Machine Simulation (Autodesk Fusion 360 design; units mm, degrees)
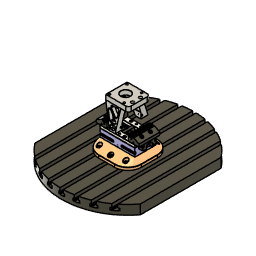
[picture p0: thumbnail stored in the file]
parameter "minJawOpening" = -31.6941 comment "Minimum Jaw Opening"
parameter "maxJawOpening" = 0 comment "Maximum Jaw Opening"
parameter "stockX" = 165.1 comment "Stock in X"
parameter "stockY" = 114.3 comment "Stock in Y"
parameter "stockZ" = 120.65 comment "Stock in Z"
base_feature "Base Feature1" OffsetX 0 OffsetY 0 OffsetZ 0 AngleZ 0
base_feature "Base Feature1"
base_feature "Base Feature1"
base_feature "Base Feature1"
base_feature "Base Feature1"
base_feature "Base Feature1"
base_feature "Base Feature1"
base_feature "Base Feature1"
base_feature "Base Feature1" OffsetX 0 OffsetY 0 OffsetZ 0 AngleZ 0 OffsetX 0 OffsetY 0 OffsetZ 0 AngleZ 0 OffsetX 0 OffsetY 0 OffsetZ 0 AngleZ 0 OffsetX 0 OffsetY 0 OffsetZ 0 AngleZ 0 OffsetX 0 OffsetY 0 OffsetZ 0 AngleZ 0
base_feature "Base Feature1" OffsetX 0 OffsetY 0 OffsetZ 0 AngleZ 0 OffsetX 0 OffsetY 0 OffsetZ 0 AngleZ 0 OffsetX 0 OffsetY 0 OffsetZ 0 AngleZ 0 OffsetX 0 OffsetY 0 OffsetZ 0 AngleZ 0 OffsetX 0 OffsetY 0 OffsetZ 0 AngleZ 0
base_feature "Base Feature1"
base_feature "Base Feature1"
base_feature "Base Feature1"
base_feature "Base Feature1"
as_built_joint "As-built1"
as_built_joint "As-built1"
as_built_joint "As-built1"
as_built_joint "As-built1"
as_built_joint "As-built1"
as_built_joint "As-built1"
joint "Assemble1" alignAngle 0 alignOffsetX 0 alignOffsetY 0 alignOffsetZ 0
as_built_joint "As-built3"
as_built_joint "As-built5"
as_built_joint "As-built6" OffsetX 0 OffsetY 0 OffsetZ 0 AngleZ 0
as_built_joint "As-built7" OffsetX 0 OffsetY 0 OffsetZ 0 AngleZ 0
work_plane "WorkPlane1" AlongDistance 0
joint_origin "JointOrigin1" OffsetX 0 OffsetY 0 OffsetZ 75.463 AngleZ 0
sketch "Sketch1" plane through (0, 0, 0) normal (0, 1, 0) x axis (1, 0, 0)
  line L1 (-15.24, -30.48) -> (-180.34, -30.48)
  line L2 (-15.24, 83.82) -> (-15.24, -30.48)
  line L3 (-180.34, 83.82) -> (-15.24, 83.82)
  line L4 (-180.34, -30.48) -> (-180.34, 83.82)
  point P2 (-180.34, -30.48)
  point P5 (-180.34, 83.82)
  point P3 (-15.24, -30.48)
  horizontal L1
  vertical L2
  horizontal L3
  vertical L4
  dimension "d111" distance P2 P5 = 114.3 (= "stockY")
  dimension "d112" distance P2 P3 = 165.1 (= "stockX")
  dimension "d318" OffsetX = 0
  dimension "d319" OffsetY = 0
  dimension "d320" OffsetZ = 0
  dimension "d321" AngleZ = 0
extrude "Extrude1" new body sketch "Sketch1" along normal blind 120.65 (= "stockZ")
joint_origin "JointOrigin1" OffsetX 0 OffsetY 0 OffsetZ 0 AngleZ 0
joint "Assemble2" alignAngle 0 alignOffsetX 0 alignOffsetY 0 alignOffsetZ 0
motion_link "MotionLink1" Value1 10.0076 Value2 10.0076
joint "Assemble3" alignAngle 180 alignOffsetX 0 alignOffsetY 0 alignOffsetZ 101.6 (= "stockY - 0.5 in")
base_feature "Base Feature1"
base_feature "Base Feature1"
joint "Assemble4" alignAngle 180 alignOffsetX 0 alignOffsetY 0 alignOffsetZ 0
joint "Assemble5" alignAngle 0 alignOffsetX 0 alignOffsetY 0 alignOffsetZ 0
base_feature "Base Feature1"
joint "Assemble6" alignAngle -90 alignOffsetX 0 alignOffsetY 0 alignOffsetZ 0
base_feature "Base Feature1"
joint_origin "JointOrigin1" OffsetX 0 named "d201_1" OffsetY 0 named "d202_1" OffsetZ 0 named "d203_1" AngleZ 0 named "d204_1"
base_feature "Base Feature1"
joint_origin "JointOrigin1" OffsetX 0 named "d201_2" OffsetY 0 named "d202_2" OffsetZ 0 named "d203_2" AngleZ 0 named "d204_2"
joint "Assemble7" alignAngle -90 alignOffsetX 0 alignOffsetY 0 alignOffsetZ 0
joint "Assemble8" alignAngle -90 alignOffsetX 0 alignOffsetY 0 alignOffsetZ 0
copy_paste "CutPaste1"
copy_paste "CutPaste2"
copy_paste "CutPaste1"
copy_paste "CutPaste2"
copy_paste "CutPaste3"
base_feature "Base Feature1"
joint_origin "JointOrigin1" OffsetX 0 named "d201_2_1" OffsetY 0 named "d202_2_1" OffsetZ 0 named "d203_2_1" AngleZ 0 named "d204_2_1"
joint_origin "JointOrigin2" OffsetX 0 named "d213_1" OffsetY 0 named "d214_1" OffsetZ 0 named "d215_1" AngleZ 0 named "d216_1"
base_feature "Base Feature1"
joint_origin "JointOrigin1" OffsetX 0 named "d201_3" OffsetY 0 named "d202_3" OffsetZ 0 named "d203_3" AngleZ 0 named "d204_3"
base_feature "Base Feature1"
joint_origin "JointOrigin1" OffsetX 0 named "d201_1_1" OffsetY 0 named "d202_1_1" OffsetZ 0 named "d203_1_1" AngleZ 0 named "d204_1_1"
joint_origin "JointOrigin2" OffsetX 0 named "d225_1" OffsetY 0 named "d226_1" OffsetZ 0 named "d227_1" AngleZ 0 named "d228_1"
joint "Assemble9" alignAngle 90 alignOffsetX 0 alignOffsetY 0 alignOffsetZ 0
joint "Assemble10" alignAngle 90 alignOffsetX 0 alignOffsetY 0 alignOffsetZ 0
joint "Assemble11" alignAngle 90 alignOffsetX 0 alignOffsetY 0 alignOffsetZ 0
copy_paste "CutPaste4"
copy_paste "CutPaste5"
copy_paste "CutPaste6"
base_feature "Base Feature1" OffsetX 0 OffsetY 0 OffsetZ 0 AngleZ 0 bodies "Table"
joint_origin "JointOrigin1" OffsetX 0 named "d149_1" OffsetY 0 named "d150_1" OffsetZ 0 named "d151_1" AngleZ 0 named "d152_1"
joint_origin "JointOrigin2" OffsetX 0 named "d153_1" OffsetY 0 named "d154_1" OffsetZ 0 named "d155_1" AngleZ 0 named "d156_1"
joint_origin "JointOrigin3" OffsetX 0 named "d157_1" OffsetY 0 named "d158_1" OffsetZ 0 named "d159_1" AngleZ 0 named "d160_1"
joint_origin "JointOrigin4" OffsetX 0 named "d161_1" OffsetY 0 named "d162_1" OffsetZ 0 named "d163_1" AngleZ 0 named "d164_1"
joint_origin "JointOrigin5" OffsetX 0 named "d165_1" OffsetY 0 named "d166_1" OffsetZ 0 named "d167_1" AngleZ 0 named "d168_1"
joint_origin "JointOrigin6" OffsetX 0 named "d169_1" OffsetY 0 named "d170_1" OffsetZ 0 named "d171_1" AngleZ 0 named "d172_1"
joint_origin "JointOrigin7" OffsetX 0 named "d173_1" OffsetY 0 named "d174_1" OffsetZ 0 named "d175_1" AngleZ 0 named "d176_1"
joint_origin "JointOrigin8" OffsetX 0 named "d177_1" OffsetY 0 named "d178_1" OffsetZ 0 named "d179_1" AngleZ 0 named "d180_1"
joint_origin "JointOrigin9" OffsetX 0 named "d181_1" OffsetY 0 named "d182_1" OffsetZ 0 named "d183_1" AngleZ 0 named "d184_1"
joint_origin "JointOrigin10" OffsetX 0 named "d185_1" OffsetY 0 named "d186_1" OffsetZ 0 named "d187_1" AngleZ 0 named "d188_1"
joint_origin "JointOrigin11" OffsetX 0 named "d189_1" OffsetY 0 named "d190_1" OffsetZ 0 named "d191_1" AngleZ 0 named "d192_1"
joint_origin "JointOrigin12" OffsetX 0 named "d193_1" OffsetY 0 named "d194_1" OffsetZ 0 named "d195_1" AngleZ 0 named "d196_1"
joint_origin "JointOrigin13" OffsetX 0 named "d197_1" OffsetY 0 named "d198_1" OffsetZ 0 named "d199_1" AngleZ 0 named "d200_1"
joint_origin "JointOrigin14" OffsetX 0 named "d201_4" OffsetY 0 named "d202_4" OffsetZ 0 named "d203_4" AngleZ 0 named "d204_4"
joint_origin "JointOrigin15" OffsetX 0 named "d205_1" OffsetY 0 named "d206_1" OffsetZ 0 named "d207_1" AngleZ 0 named "d208_1"
joint_origin "JointOrigin16" OffsetX 0 named "d209_1" OffsetY 0 named "d210_1" OffsetZ 0 named "d211_1" AngleZ 0 named "d212_1"
joint_origin "JointOrigin17" OffsetX 0 named "d213_2" OffsetY 0 named "d214_2" OffsetZ 0 named "d215_2" AngleZ 0 named "d216_2"
joint_origin "JointOrigin18" OffsetX 0 named "d217_1" OffsetY 0 named "d218_1" OffsetZ 0 named "d219_1" AngleZ 0 named "d220_1"
as_built_joint "As-built1"
joint "Assemble12" alignAngle 90 alignOffsetX 0 alignOffsetY 0 alignOffsetZ 38.1 (= "4 in - 2.5 in")
copy_paste "CutPaste1"
sketch "Sketch1" plane through (0, 0, 0) normal (0, -1, 0) x axis (1, 0, 0)
  line L1 (-50, 82.4998) -> (50, 82.4998)
  line L2 (-50, -82.4998) -> (-50, 82.4998)
  line L3 (50, -82.4998) -> (-50, -82.4998)
  line L4 (50, 82.4998) -> (50, -82.4998)
  line L5 (-50, -82.4998) -> (50, 82.4998)
  line L6 (50, -82.4998) -> (-50, 82.4998)
  point P6 (0, 0)
  point P1 (0, 0)
  point P2 (50, 82.4998)
  point P7 (50, 82.4998)
  perpendicular L1 L2
  parallel L1 L3
  parallel L2 L4
  horizontal L1
  coincident L5 P6
  coincident L6 P6
  coincident P1 P6
  coincident P2 P7
  dimension "d358" OffsetX = 0
  dimension "d359" OffsetY = 0
  dimension "d360" OffsetZ = 0
  dimension "d361" AngleZ = 0
extrude "Extrude1" new body sketch "Sketch1" profile of L1 L2 L3 L4 along normal blind 3.81
sketch "Sketch2" plane through (0, -38.1, 0) normal (0, 1, 0) x axis (-1, 0, 0)
  line L1 (-101.6, 101.6) -> (101.6, 101.6)
  line L2 (-101.6, -101.6) -> (-101.6, 101.6)
  line L3 (101.6, -101.6) -> (-101.6, -101.6)
  line L4 (101.6, 101.6) -> (101.6, -101.6)
  line L5 (-101.6, -101.6) -> (101.6, 101.6)
  line L6 (101.6, -101.6) -> (-101.6, 101.6)
  point P6 (0, 0)
  point P1 (0, 0)
  point P2 (101.6, 101.6)
  point P3 (-101.6, 101.6)
  perpendicular L1 L2
  parallel L1 L3
  parallel L2 L4
  horizontal L1
  coincident L5 P6
  coincident L6 P6
  coincident P1 P6
  equal L1 L4
  dimension "d287" distance P2 P3 = 203.2
extrude "Extrude2" new body sketch "Sketch2" profile of L1 L2 L3 L4 along normal blind 12.7
fillet "Fillet1" radius 63.5
fillet "Fillet2" radius 1.27
loft "Loft1"
sketch "Sketch3" plane through (0, -38.1, 0) normal (0, -1, 0) x axis (1, 0, 0)
  circle C1 centre (0, 0) radius 28.575
  point P1 (0, 0)
  point P2 (0, 0)
  coincident P1 P2
  dimension "d292" diameter C1 = 57.15
extrude "Extrude3" add sketch "Sketch3" along normal blind 6.35
as_built_joint "As-built8"
as_built_joint "As-built9"
sketch "Sketch2" plane through (0, 0, 0) normal (0, 0, 1) x axis (1, 0, 0)
  line L1 (482.6, 147.0957) -> (179.3748, 147.0957)
  line L2 (482.6, 58.1957) -> (482.6, 147.0957)
  line L3 (444.5, 58.1957) -> (482.6, 58.1957)
  line L4 (444.5, 80.4207) -> (444.5, 58.1957)
  line L5 (333.375, 80.4207) -> (444.5, 80.4207)
  line L6 (333.375, 110.2657) -> (333.375, 80.4207)
  line L7 (320.675, 110.2657) -> (333.375, 110.2657)
  line L8 (320.675, 115.3457) -> (320.675, 110.2657)
  line L9 (307.34, 115.3457) -> (320.675, 115.3457)
  line L10 (305.054, 124.7183) -> (307.34, 115.3457)
  line L11 (264.414, 124.7183) -> (305.054, 124.7183)
  line L12 (264.414, 128.4267) -> (264.414, 124.7183)
  line L13 (261.1628, 128.4267) -> (264.414, 128.4267)
  line L14 (261.1628, 124.7183) -> (261.1628, 128.4267)
  line L15 (255.5748, 124.7183) -> (261.1628, 124.7183)
  line L16 (255.5748, 127.1186) -> (255.5748, 124.7183)
  line L17 (217.4748, 127.1186) -> (255.5748, 127.1186)
  line L18 (217.4748, 140.7457) -> (217.4748, 127.1186)
  line L19 (179.3748, 140.7457) -> (217.4748, 140.7457)
  line L20 (179.3748, 147.0957) -> (179.3748, 140.7457)
  point P2 (179.3748, 147.0957)
  point P22 (179.3748, 147.0957)
  point P3 (482.6, 147.0957)
  point P4 (482.6, 58.1957)
  point P14 (264.414, 128.4267)
  point P15 (261.1628, 128.4267)
  point P5 (444.5, 58.1957)
  point P6 (444.5, 80.4207)
  point P7 (333.375, 80.4207)
  point P8 (333.375, 110.2657)
  point P9 (320.675, 110.2657)
  point P10 (320.675, 115.3457)
  point P11 (307.34, 115.3457)
  point P12 (305.054, 124.7183)
  point P13 (264.414, 124.7183)
  point P16 (261.1628, 124.7183)
  point P17 (255.5748, 124.7183)
  point P20 (217.4748, 140.7457)
  point P21 (179.3748, 140.7457)
  point P18 (255.5748, 127.1186)
  point P19 (217.4748, 127.1186)
  horizontal L1
  perpendicular L1 L2
  perpendicular L2 L3
  perpendicular L1 L4
  perpendicular L2 L5
  perpendicular L1 L6
  perpendicular L6 L7
  perpendicular L7 L8
  perpendicular L8 L9
  perpendicular L8 L11
  perpendicular L11 L12
  perpendicular L12 L13
  perpendicular L13 L14
  perpendicular L14 L15
  perpendicular L15 L16
  collinear L11 L15
  perpendicular L17 L18
  perpendicular L18 L19
  perpendicular L19 L20
  coincident P2 P22
  dimension "d295" distance P3 P4 = 88.9
  dimension "d296" distance L1 L5 = 66.675 (= "( 5.25 / 2 ) * 1 in")
  dimension "d297" distance L1 L7 = 36.83 (= "( 2.9 / 2 ) * 1 in")
  dimension "d298" distance L1 L9 = 31.75 (= "( 2.5 / 2 ) * 1 in")
  dimension "d299" distance L1 L11 = 22.3774 (= "( 1.762 / 2 ) * 1 in")
  dimension "d300" distance L1 L13 = 18.669 (= "( 1.47 / 2 ) * 1 in")
  dimension "d301" distance L1 L17 = 19.9771 (= "( 1.573 / 2 ) * 1 in")
  dimension "d302" distance P14 P15 = 3.2512
  dimension "d303" distance P4 P5 = 38.1
  dimension "d304" distance P6 P7 = 111.125
  dimension "d305" distance P8 P9 = 12.7
  dimension "d306" distance P10 P11 = 13.335
  dimension "d307" distance P11 P12 = 2.286
  dimension "d308" distance P12 P13 = 40.64
  dimension "d309" distance P16 P17 = 5.588
  dimension "d310" distance L1 L19 = 6.35
  dimension "d311" distance P20 P21 = 38.1
  dimension "d312" distance P18 P19 = 38.1
revolve "Revolve1" sketch "Sketch2" AlongAngle 360
component_from_bodies "Body->Comp"
joint "Assemble13" alignAngle 180 alignOffsetX 0 alignOffsetY -15.24 alignOffsetZ -12.7
copy_paste "CutPaste2"
copy_paste "CutPaste3"
sketch "Sketch4" plane through (0, -38.1, 0) normal (0, -1, 0) x axis (1, 0, 0)
  line L1 (-191.6377, 250) -> (191.6377, 250)
  line L2 (191.6377, -250) -> (-191.6377, -250)
  line L3 (310.1389, -55.126) -> (9.652, -55.126)
  line L4 (9.652, -70.874) -> (306.9232, -70.874)
  circle C1 centre (-73.025, 63) radius 6.6675
  circle C2 centre (73.025, 63) radius 6.6675
  circle C3 centre (82.55, 0) radius 6.6675
  circle C4 centre (-82.55, 0) radius 6.6675
  circle C5 centre (-73.025, -63) radius 6.6675
  circle C6 centre (73.025, -63) radius 6.6675
  arc A1 centre (0, 0) radius 315 clockwise from (191.6377, 250) to (191.6377, -250)
  arc A2 centre (0, 0) radius 315 clockwise from (-191.6377, -250) to (-191.6377, 250)
  circle C7 centre (59.8029, -16.0241) radius 6.7437
  circle C8 centre (-16.0241, -59.8029) radius 6.7437
  circle C9 centre (-43.7787, -43.7787) radius 6.7437
  circle C10 centre (-43.7787, 43.7787) radius 6.7437
  circle C11 centre (-16.0241, 59.8029) radius 6.7437
  circle C12 centre (59.8029, 16.0241) radius 6.7437
  circle C13 centre (0, 0) radius 0.4391
  arc A3 centre (-60.96, 63) radius 7.874 clockwise from (-60.96, 70.874) to (-60.96, 55.126)
  arc A4 centre (9.652, 63) radius 7.874 clockwise from (9.652, 55.126) to (9.652, 70.874)
  arc A5 centre (9.652, -63) radius 7.874 clockwise from (9.652, -70.874) to (9.652, -55.126)
  arc A6 centre (0, 0) radius 315 clockwise from (310.1389, -55.126) to (306.9232, -70.874)
  arc A7 centre (-60.96, -63) radius 7.874 clockwise from (-60.96, -55.126) to (-60.96, -70.874)
  arc A8 centre (-42.672, 0) radius 7.874 clockwise from (-42.672, 7.874) to (-42.672, -7.874)
  arc A9 centre (80.01, 0) radius 7.874 clockwise from (80.01, -7.874) to (80.01, 7.874)
  point P3 (73.025, 63)
  point P24 (9.652, 63)
  point P2 (-73.025, 63)
  point P7 (73.025, -63)
  point P27 (9.652, -63)
  point P6 (-73.025, -63)
  point P4 (82.55, 0)
  point P39 (80.01, 0)
  point P5 (-82.55, 0)
  point P36 (-42.672, 0)
  point P1 (0, 0)
  equal C5 C6
  equal C4 C5
  equal C1 C4
  equal C1 C2
  equal C2 C3
  horizontal P3 P24
  horizontal P2 P3
  horizontal P7 P27
  horizontal P6 P7
  vertical P2 P6
  vertical P3 P7
  horizontal P4 P39
  horizontal P5 P36
  dimension "d342" diameter C1 = 13.335
  dimension "d343" distance P1 P7 = 73.025
  dimension "d344" distance P1 P6 = 73.025 (= "d343")
  dimension "d346" distance P1 P5 = 82.55
  dimension "d347" distance P1 P4 = 82.55 (= "d346")
extrude "Extrude4" cut sketch "Sketch4" profile of C1 C2 C3 C4 C5 C6 A9 no distance stored
work_plane "WorkPlane1" AlongDistance -6.35
sketch "Sketch5" plane through (0, -31.75, 0) normal (0, -1, 0) x axis (1, 0, 0)
  circle C1 centre (73.025, 63) radius 9.8425
  circle C2 centre (73.025, 63) radius 6.6675
  circle C3 centre (82.55, 0) radius 9.8425
  circle C4 centre (73.025, -63) radius 9.8425
  circle C5 centre (-73.025, -63) radius 9.8425
  circle C6 centre (-82.55, 0) radius 9.8425
  circle C7 centre (-73.025, 63) radius 9.8425
  circle C8 centre (-73.025, 63) radius 6.6675
  circle C9 centre (-82.55, 0) radius 6.6675
  circle C10 centre (-73.025, -63) radius 6.6675
  circle C11 centre (73.025, -63) radius 6.6675
  circle C12 centre (82.55, 0) radius 6.6675
  concentric C1 C2
  equal C6 C7
  equal C5 C6
  equal C4 C5
  equal C3 C4
  equal C1 C3
  concentric C7 C8
  concentric C6 C9
  concentric C5 C10
  concentric C4 C11
  concentric C3 C12
  dimension "d349" diameter C1 = 19.685
extrude "Extrude5" cut sketch "Sketch5" no distance stored
chamfer "Chamfer1" distance 0.762
chamfer "Chamfer2" distance 0.762
base_feature "Base Feature1" OffsetX 0 OffsetY 0 OffsetZ 0 AngleZ 0
joint "Assemble14" alignAngle 0 alignOffsetX 0 alignOffsetY 0 alignOffsetZ 0
base_feature "Base Feature1" OffsetX 0 named "d354_1" OffsetY 0 named "d355_1" OffsetZ 0 named "d356_1" AngleZ 0 named "d357_1"
joint_origin "JointOrigin2" OffsetX 0 named "d366_1" OffsetY 0 named "d367_1" OffsetZ 0 named "d368_1" AngleZ 0 named "d369_1"
base_feature "Base Feature1" OffsetX 0 named "d354_2" OffsetY 0 named "d355_2" OffsetZ 0 named "d356_2" AngleZ 0 named "d357_2"
joint_origin "JointOrigin2" OffsetX 0 named "d366_2" OffsetY 0 named "d367_2" OffsetZ 0 named "d368_2" AngleZ 0 named "d369_2"
base_feature "Base Feature1" OffsetX 0 named "d354_3" OffsetY 0 named "d355_3" OffsetZ 0 named "d356_3" AngleZ 0 named "d357_3"
joint_origin "JointOrigin2" OffsetX 0 named "d366_3" OffsetY 0 named "d367_3" OffsetZ 0 named "d368_3" AngleZ 0 named "d369_3"
base_feature "Base Feature1" OffsetX 0 named "d354_4" OffsetY 0 named "d355_4" OffsetZ 0 named "d356_4" AngleZ 0 named "d357_4"
joint_origin "JointOrigin2" OffsetX 0 named "d366_4" OffsetY 0 named "d367_4" OffsetZ 0 named "d368_4" AngleZ 0 named "d369_4"
base_feature "Base Feature1" OffsetX 0 named "d354_5" OffsetY 0 named "d355_5" OffsetZ 0 named "d356_5" AngleZ 0 named "d357_5"
joint_origin "JointOrigin2" OffsetX 0 named "d366_5" OffsetY 0 named "d367_5" OffsetZ 0 named "d368_5" AngleZ 0 named "d369_5"
joint "Assemble15" alignAngle 0 alignOffsetX 0 alignOffsetY 0 alignOffsetZ 0
joint "Assemble16" alignAngle 0 alignOffsetX 0 alignOffsetY 0 alignOffsetZ 0
joint "Assemble17" alignAngle 0 alignOffsetX 0 alignOffsetY 0 alignOffsetZ 0
joint "Assemble18" alignAngle 0 alignOffsetX 0 alignOffsetY 0 alignOffsetZ 0
joint "Assemble19" alignAngle 0 alignOffsetX 0 alignOffsetY 0 alignOffsetZ 0
copy_paste "CutPaste4"
copy_paste "CutPaste5"
copy_paste "CutPaste6"
copy_paste "CutPaste7"
copy_paste "CutPaste8"
copy_paste "CutPaste9"
sketch "Sketch2" plane through (0, 0, 0) normal (0, -1, 0) x axis (1, 0, 0)
  line L1 (-50, 82.4998) -> (50, 82.4998)
  line L2 (-50, -82.4998) -> (-50, 82.4998)
  line L3 (50, -82.4998) -> (-50, -82.4998)
  line L4 (50, 82.4998) -> (50, -82.4998)
  line L5 (-50, -82.4998) -> (50, 82.4998)
  line L6 (50, -82.4998) -> (-50, 82.4998)
  point P6 (0, 0)
  point P1 (0, 0)
  point P2 (50, 82.4998)
  point P7 (50, 82.4998)
  perpendicular L1 L2
  parallel L1 L3
  parallel L2 L4
  horizontal L1
  coincident L5 P6
  coincident L6 P6
  coincident P1 P6
  coincident P2 P7
extrude "Extrude2" new body sketch "Sketch2" profile of L1 L2 L3 L4 along normal blind 2.54
fillet "Fillet2" radius 1.27
as_built_joint "As-built10"
remove_instance "RemoveInstance18"
base_feature "Base Feature1"
position "Position32"
joint "Assemble21" OffsetX 0 OffsetY 0 OffsetZ 0 AngleZ 0 alignAngle 180 alignOffsetX 0 alignOffsetY 0 alignOffsetZ -114.0572
as_built_joint "As-built12"
sketch "Side Containment" plane through (82.55, 0, 6.35) normal (1, 0, 0) x axis (0, 1, 0)
  line L1 (75.463, -63.5) -> (75.463, 50.8)
  line L2 (196.113, -63.5) -> (75.463, -63.5)
  line L3 (196.113, 50.8) -> (196.113, -63.5)
  line L4 (75.463, 50.8) -> (196.113, 50.8)
  line L5 (79.5905, 95.25) -> (231.9905, 95.25)
  line L6 (79.5905, 39.37) -> (79.5905, 95.25)
  line L7 (55.0926, 39.37) -> (79.5905, 39.37)
  line L8 (55.0926, -52.07) -> (55.0926, 39.37)
  line L9 (79.5905, -52.07) -> (55.0926, -52.07)
  line L10 (79.5905, -107.95) -> (79.5905, -52.07)
  line L11 (231.9905, -107.95) -> (79.5905, -107.95)
  line L12 (231.9905, 95.25) -> (231.9905, -107.95)
  line L13 (48.4465, 0) -> (48.4465, -12.7)
  line L14 (231.9905, -6.35) -> (48.4465, -6.35)
  line L15 (50.063, 44.45) -> (75.463, 44.45)
  line L16 (50.0126, 75.3878) -> (50.0126, -88.0878)
  line L17 (77.0505, 51.054) -> (77.0505, 63.246)
  point P16 (48.4465, -6.35)
  point P17 (231.9905, -6.35)
  point P6 (231.9905, 95.25)
  point P13 (231.9905, -107.95)
  point P7 (79.5905, 95.25)
  horizontal L5
  perpendicular L4 L6
  perpendicular L1 L7
  perpendicular L4 L8
  perpendicular L8 L9
  perpendicular L4 L10
  perpendicular L8 L11
  vertical L12
  midpoint L13 P16
  coincident L12 P17
  perpendicular L12 L14
  midpoint L12 P17
  equal L6 L10
  collinear L6 L10
  dimension "d464" distance L7 L15 = 5.08
  dimension "d465" distance L8 L16 = 5.08
  dimension "d466" distance L6 L17 = 2.54
  dimension "d467" distance P6 P13 = 203.2
  dimension "d468" distance P6 P7 = 152.4
base_feature "Base Feature1"
joint "Assemble22" OffsetX 0 OffsetY 0 OffsetZ 0 AngleZ 0 OffsetX 0 OffsetY 0 OffsetZ 0 AngleZ 0 alignAngle 0 alignOffsetX 0 alignOffsetY -6.35 alignOffsetZ 0
sketch "Sketch4" plane through (0, -38.1, 0) normal (0, 1, 0) x axis (-1, 0, 0)
  line L1 (245.7959, 197.001) -> (-245.7959, 197.001)
  line L2 (-191.6377, 250) -> (191.6377, 250)
  arc A1 centre (0, 0) radius 315 clockwise from (191.6377, 250) to (245.7959, 197.001)
  arc A2 centre (0, 0) radius 315 clockwise from (-245.7959, 197.001) to (-191.6377, 250)
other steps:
base_feature "Base Feature1" OffsetX 0 OffsetY 0 OffsetZ 0 AngleZ 0
create_component "CreateComponent1"
create_component "CreateComponent1"
create_component "CreateComponent2"
create_component "CreateComponent3"
create_component "CreateComponent4"
create_component "CreateComponent5"
create_component "CreateComponent6"
create_component "CreateComponent7"
create_component "CreateComponent2"
create_component "CreateComponent1"
create_component "CreateComponent2"
create_component "CreateComponent3"
create_component "CreateComponent1"
create_component "CreateComponent4"
create_component "CreateComponent1"
create_component "CreateComponent2"
create_component "CreateComponent5"
create_component "CreateComponent1"
create_component "CreateComponent6"
joint_origin "JointOrigin1" OffsetX 0 OffsetY 0 OffsetZ 0 AngleZ 0
joint_origin "JointOrigin1" OffsetX 0 OffsetY 0 OffsetZ 0 AngleZ 0
create_component "CreateComponent7"
joint_origin "JointOrigin6" OffsetX 0 OffsetY 0 OffsetZ 0 AngleZ 0
joint_origin "JointOrigin6" OffsetX 0 OffsetY 0 OffsetZ 0 AngleZ 0
create_component "CreateComponent8"
create_component "CreateComponent9"
joint_origin "JointOrigin1" OffsetX 0 OffsetY 0 OffsetZ 0 AngleZ 0
joint_origin "JointOrigin7" OffsetX 0 OffsetY 0 OffsetZ 0 AngleZ 0
joint_origin "JointOrigin1" OffsetX 0 OffsetY 0 OffsetZ 0 AngleZ 0
joint_origin "JointOrigin7" OffsetX 0 OffsetY 0 OffsetZ 0 AngleZ 0
create_component "CreateComponent10"
joint_origin "JointOrigin1" OffsetX 0 OffsetY 0 OffsetZ 0 AngleZ 0
joint_origin "JointOrigin8" OffsetX 0 OffsetY 0 OffsetZ 0 AngleZ 0
create_component "CreateComponent11"
create_component "CreateComponent12"
joint_origin "JointOrigin2" OffsetX 0 OffsetY 0 OffsetZ 0 AngleZ 0
joint_origin "JointOrigin9" OffsetX 0 OffsetY 0 OffsetZ 0 AngleZ 0
joint_origin "JointOrigin2" OffsetX 0 OffsetY 0 OffsetZ 0 AngleZ 0
joint_origin "JointOrigin10" OffsetX 0 OffsetY 0 OffsetZ 0 AngleZ 0
create_component "CreateComponent13"
remove_instance "RemoveInstance1"
remove_instance "RemoveInstance2"
create_component "CreateComponent14"
remove_instance "RemoveInstance3"
remove_instance "RemoveInstance4"
remove_instance "RemoveInstance5"
create_component "CreateComponent15"
create_component "CreateComponent16"
create_component "CreateComponent17"
joint_origin "JointOrigin2" OffsetX 0 OffsetY 0 OffsetZ 0 AngleZ 0
joint_origin "JointOrigin8" OffsetX 0 OffsetY 0 OffsetZ 0 AngleZ 0
joint_origin "JointOrigin3" OffsetX 0 OffsetY 0 OffsetZ 0 AngleZ 0
joint_origin "JointOrigin9" OffsetX 0 OffsetY 0 OffsetZ 0 AngleZ 0
joint_origin "JointOrigin3" OffsetX 0 OffsetY 0 OffsetZ 0 AngleZ 0
joint_origin "JointOrigin10" OffsetX 0 OffsetY 0 OffsetZ 0 AngleZ 0
remove_instance "RemoveInstance6"
remove_instance "RemoveInstance7"
remove_instance "RemoveInstance8"
create_component "CreateComponent18"
create_component "CreateComponent1"
create_component "CreateComponent19"
remove_instance "RemoveInstance9"
create_component "CreateComponent20"
create_component "CreateComponent21"
remove_body "RemoveBody1"
joint_origin "JointOrigin3" OffsetX 0 OffsetY 0 OffsetZ 0 AngleZ 0
joint_origin "JointOrigin20" OffsetX 0 OffsetY 0 OffsetZ 0 AngleZ 0
joint_origin "JointOrigin2" OffsetX 0 OffsetY 0 OffsetZ 0 AngleZ 0
joint_origin "JointOrigin3" OffsetX 0 OffsetY 0 OffsetZ 0 AngleZ 0
remove_instance "RemoveInstance10"
remove_instance "RemoveInstance11"
create_component "CreateComponent22"
joint_origin "JointOrigin2" OffsetX 0 OffsetY 0 OffsetZ 0 AngleZ 0
joint_origin "JointOrigin2" OffsetX 0 OffsetY 0 OffsetZ 0 AngleZ 0
create_component "CreateComponent23"
create_component "CreateComponent24"
create_component "CreateComponent25"
create_component "CreateComponent26"
create_component "CreateComponent27"
joint_origin "JointOrigin3" OffsetX 0 OffsetY 0 OffsetZ 0 AngleZ 0
joint_origin "JointOrigin3" OffsetX 0 OffsetY 0 OffsetZ 0 AngleZ 0
joint_origin "JointOrigin3" OffsetX 0 OffsetY 0 OffsetZ 0 AngleZ 0
joint_origin "JointOrigin4" OffsetX 0 OffsetY 0 OffsetZ 0 AngleZ 0
joint_origin "JointOrigin3" OffsetX 0 OffsetY 0 OffsetZ 0 AngleZ 0
joint_origin "JointOrigin5" OffsetX 0 OffsetY 0 OffsetZ 0 AngleZ 0
joint_origin "JointOrigin3" OffsetX 0 OffsetY 0 OffsetZ 0 AngleZ 0
joint_origin "JointOrigin6" OffsetX 0 OffsetY 0 OffsetZ 0 AngleZ 0
joint_origin "JointOrigin3" OffsetX 0 OffsetY 0 OffsetZ 0 AngleZ 0
joint_origin "JointOrigin7" OffsetX 0 OffsetY 0 OffsetZ 0 AngleZ 0
remove_instance "RemoveInstance12"
remove_instance "RemoveInstance13"
remove_instance "RemoveInstance14"
remove_instance "RemoveInstance15"
remove_instance "RemoveInstance16"
remove_instance "RemoveInstance17"
create_component "CreateComponent29"
joint_origin "JointOrigin4" OffsetX 0 OffsetY 0 OffsetZ 0 AngleZ 0
create_component "CreateComponent30"
create_component "CreateComponent31"
named bodies: "Table"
